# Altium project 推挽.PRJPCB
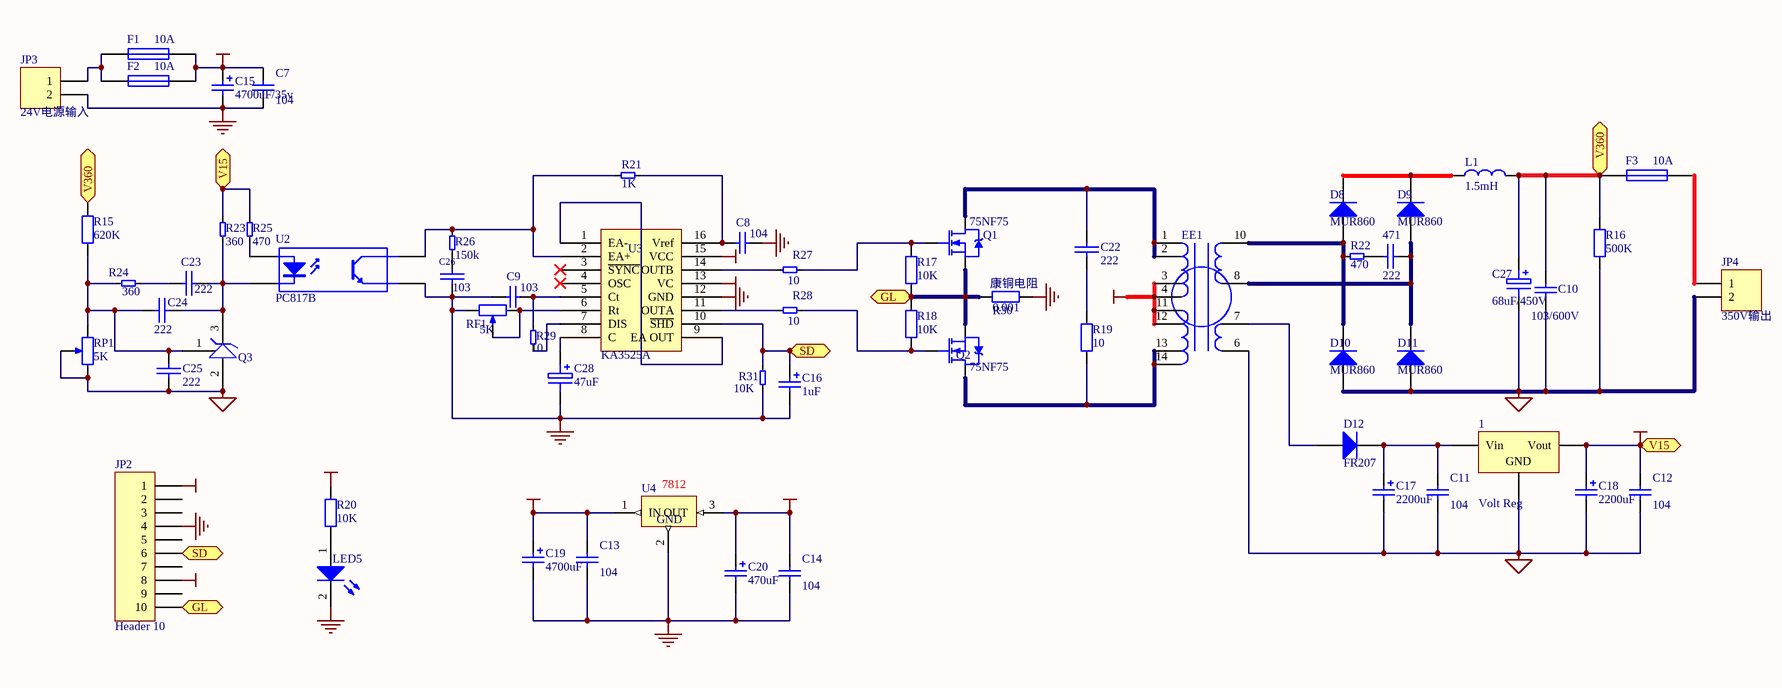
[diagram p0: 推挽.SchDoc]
1 sheet, 62 parts. Net scope: flat (ports and power ports of the same name join across sheets).
Board file: 推挽.PcbDoc

## Sheet 推挽.SchDoc
size B

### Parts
1  Volt Reg  [SFM-T3/X1.6V]
471  222  [RAD-0.2]
C7  value 104  [RAD-0.2]  (hidden comment: Cap)
C8  value 104  [RAD-0.1]  (hidden comment: Cap)
C9  value 103  [RAD-0.1]  (hidden comment: Cap)
C10  value 103/600V  [RAD-0.2]  (hidden comment: Cap)
C11  value 104  [RAD-0.1]  (hidden comment: Cap)
C12  value 104  [RAD-0.1]  (hidden comment: Cap)
C13  value 104  [RAD-0.1]  (hidden comment: Cap)
C14  value 104  [RAD-0.1]  (hidden comment: Cap)
C15  value 4700uF/35v  [RB.3/.6]  (hidden comment: Cap Pol1)
C16  value 1uF  [rb.1/.2]  (hidden comment: Cap Pol1)
C17  value 2200uF  [RB.2/.4]  (hidden comment: Cap Pol1)
C18  value 2200uF  [RB.2/.4]  (hidden comment: Cap Pol1)
C19  value 4700uF  [RB.3/.6]  (hidden comment: Cap Pol1)
C20  value 470uF  [RB.2/.4]  (hidden comment: Cap Pol1)
C22  222  [RAD-0.2]
C23  222  [rad-0.1]
C24  222  [rad-0.1]
C25  222  [rad-0.1]
C26  103  [RAD-0.1]
C27  68uF/450V  [100uF/450V]
C28  47uF  [RB.1/.2]
D8  MUR860  [RHRP8120]
D9  MUR860  [RHRP8120]
D10  MUR860  [RHRP8120]
D11  MUR860  [RHRP8120]
D12  FR207  [diode-0.4]
EE1  (no value)  [EE44]
F1  10A  [FUSE]
F2  10A  [FUSE]
F3  10A  [axial-0.6]
JP2  Header 10  [HDR1X10]
JP3  24V电源输入  [JK128-500-2P]
JP4  350V输出  [JK128-500-2P]
L1  1.5mH  [1mH]
LED5  LED0  [RAD-0.1]  (value not drawn)
Q1  75NF75  [SFM-T3/X1.6V]
Q2  75NF75  [SFM-T3/X1.6V]
Q3  TL431  [TO-92A]  (value not drawn)
R15  value 620K  [AXIAL-0.8]  (hidden comment: Res2)
R16  value 500K  [AXIAL-0.8]  (hidden comment: Res2)
R17  value 10K  [AXIAL-0.4]  (hidden comment: Res2)
R18  value 10K  [AXIAL-0.4]  (hidden comment: Res2)
R19  value 10  [AXIAL-0.4]  (hidden comment: Res2)
R20  value 10K  [AXIAL-0.4]  (hidden comment: Res2)
R21  value 1K  [AXIAL-0.4]  (hidden comment: 1.2K)
R22  value 470  [AXIAL-0.4]  (hidden comment: 1.2K)
R23  360  [AXIAL-0.4]
R24  360  [AXIAL-0.4]
R25  470  [AXIAL-0.4]
R26  150k  [AXIAL-0.4]
R27  value 10  [AXIAL-0.4]
R28  value 10  [AXIAL-0.4]
R29  value 10  [AXIAL-0.4]
R30  康铜电阻  value 0.001  [AXIAL-0.8]
R31  10K  [AXIAL-0.4]
RF1  value 5K  [VR5]  (hidden comment: RPot2)
RP1  value 5K  [VR5]  (hidden comment: RPot2)
U2  PC817B  [DIP-4]
U3  KA3525A  [dip-16]
U4  7812  [SFM-T3/X1.6V]

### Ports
GL, SD, V15, V360

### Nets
15V: 1.3(Vout) C12.2 C18.1 R23.2 R25.2 ; port V15
GND: C7.1 C8.1 C9.2 C13.1 C14.1 C15.2 C16.2 C19.2 C20.2 C26.2 C28.2 JP2.4 JP3.2 LED5.2(K) R30.1 R31.1 RF1.1(TOP) U2.3(E) U3.12(GND) U4.2(GND)
SGND: 1.2(GND) C10.1 C11.1 C12.1 C17.2 C18.2 C25.1 C27.2 D10.1(A) D11.1(A) EE1.6 JP4.2 Q3.2 R16.1 RP1.2(BOT) RP1.3(TAP)
VCC+12V: C14.2 C20.1 JP2.8 R20.1 U3.13(VC) U3.15(VCC) U4.3(OUT)
VCC+24V: C7.2 C13.2 C15.1 C19.1 EE1.3 EE1.4 EE1.11 EE1.12 F1.2 F2.2 JP2.1 U4.1(IN)
Net1_1: 1.1(Vin) C11.2 C17.1 D12.2(K)
Net471_1: 471.1 R22.1
Net471_2: 471.2 D9.1(A) D11.2(K) EE1.8
NetC8_2: C8.2 R21.1 U3.16(Vref)
NetC9_1: C9.1 R29.1 U3.5(Ct)
NetC10_2: C10.2 C27.1 F3.1 L1.1 R15.2 R16.2 ; port V360
NetC16_1: C16.1 JP2.6 R31.2 U3.10(~{SHD}) ; port SD
NetC22_1: C22.1 EE1.1 EE1.2 Q1.2(D)
NetC22_2: C22.2 R19.2
NetC23_1: C23.1 R24.1
NetC23_2: C23.2 C24.2 Q3.3 R23.1 U2.2(K)
NetC24_1: C24.1 C25.2 Q3.1 R15.1 R24.2 RP1.1(TOP)
NetC26_1: C26.1 R26.2
NetC28_1: C28.1 U3.8(C)
NetD8_1: D8.1(A) D10.2(K) EE1.10 R22.2
NetD8_2: D8.2(K) D9.2(K) L1.2
NetD12_1: D12.1(A) EE1.7
NetEE1_13: EE1.13 EE1.14 Q2.2(D) R19.1
NetF1_1: F1.1 F2.1 JP3.1
NetF3_2: F3.2 JP4.1
NetJP2_10: JP2.10 Q1.3(S) Q2.3(S) R17.1 R18.1 R30.2 ; port GL
NetLED5_1: LED5.1(A) R20.2
NetQ1_1: Q1.1(G) R17.2 R27.2
NetQ2_1: Q2.1(G) R18.2 R28.2
NetR21_2: R21.2 R26.1 U2.4(C) U3.2(EA+)
NetR25_1: R25.1 U2.1(A)
NetR27_1: R27.1 U3.14(OUTB)
NetR28_1: R28.1 U3.11(OUTA)
NetR29_2: R29.2 U3.7(DIS)
NetRF1_2: RF1.2(TAP) RF1.3(BOT) U3.6(Rt)
NetU3_1: U3.1(EA-) U3.9(EA_OUT)

Not connected (* = marked no-connect by the designer): JP2 2 3 5 7 9; U3 3(~{SYNC})* 4(OSC)*

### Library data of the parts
1 = Volt Reg: Voltage Regulator; Manufacturer: Generic Components; Class: Power Management
471 C22-C26 = CAP: Capacitor
C7-C14 = Cap: Capacitor; Manufacturer: Generic Components; Class: Passive
C15-C20 = Cap Pol1: Polarized Capacitor (Radial); Manufacturer: Generic Components; Class: Passive
C27 = 22UF/35V_E: CCER1-226S035
C28 = 4.7UF/400V_E: CCER2-475S400
D8-D12 = Diode: Default Diode; Manufacturer: Generic Components; Class: Discrete; SubClass: Diode - Switching
EE1 = EE44: pin to pad: 10>9
F1-F3 = Fuse 1: Fuse; Manufacturer: Generic Components; Class: Passive
JP2 = Header 10: Header, 10-Pin; Manufacturer: Generic Components; Class: Connector
JP3 JP4 = Header 2: Header, 2-Pin; Manufacturer: Generic Components; Class: Connector
L1 = 6.8UH: CL-NLFC3225-6R8
LED5 = LED0: Typical INFRARED GaAs LED; Manufacturer: Generic Components; Class: Optoelectronic
Q1 Q2 = IRF840: CQ-IRF840
R15-R20 R30 = Res2: Resistor; Manufacturer: Generic Components; Class: Passive
R21-R29 R31 = 1.1K: CR85-112J
RF1 RP1 = RPot2: Potentiometer; Manufacturer: Generic Components; Class: Passive; Set Position: 0.5
U2 = PC817C
U4 = LM7812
